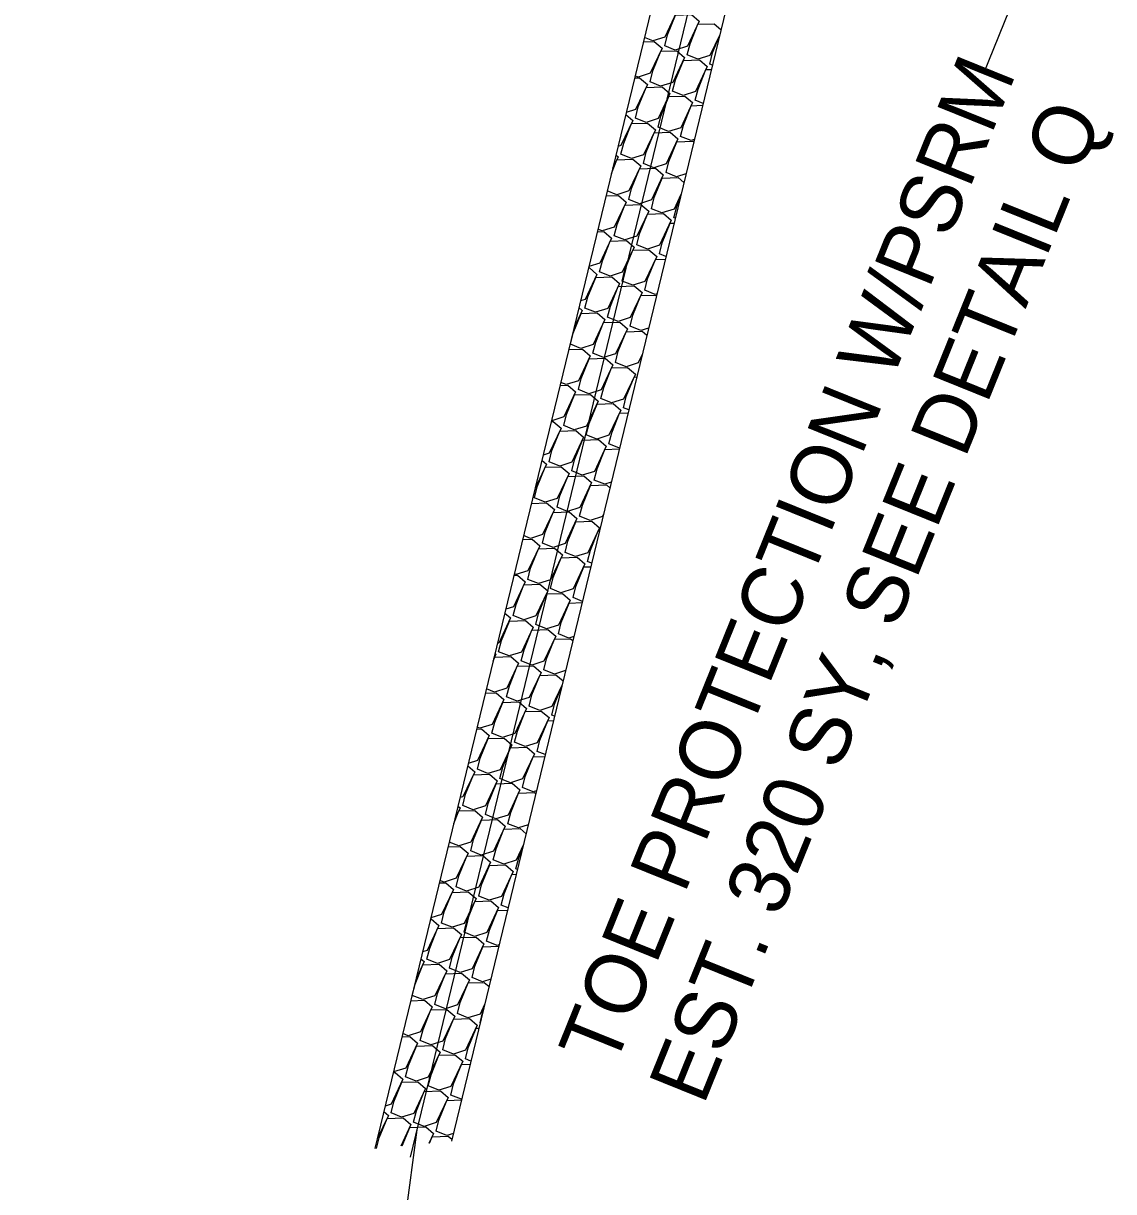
# Model space of a CAD drawing. Extents: x 2384780 to 2405432, y 547869 to 573706.
# Drawn here: x 2395368.5 to 2395458.5, y 556433.7 to 556530.2 of the extents above; entities that cross this region are included whole.
import ezdxf

# ---------------------------------------------------------------- set-up
doc = ezdxf.new("R2010")
doc.units = 0
for name, color, linetype in [('Old_Level_18', 7, 'Continuous'), ('Old_Level_19', 7, 'Continuous'), ('Old_Level_20', 7, 'Continuous'), ('Old_Level_5', 7, 'Continuous')]:
    doc.layers.add(name, color=color, linetype=linetype)

msp = doc.modelspace()

# ---------------------------------------------------------------- linework, layer by layer
at = {"layer": 'Old_Level_18'}
msp.add_line((2395437.477, 556589.14), (2395400.485, 556436.558), dxfattribs=at)
at = {"layer": 'Old_Level_19'}
msp.add_line((2395401.03, 556438.804), (2395368.546, 556196.083), dxfattribs=at)
at = {"layer": 'Old_Level_20'}
for p, q in [((2395434.562, 556589.846), (2395397.57, 556437.265)), ((2395440.393, 556588.433), (2395403.889, 556437.867))]:
    msp.add_line(p, q, dxfattribs=at)
for points in [[(2395420.339, 556531.18), (2395420.508, 556531.601), (2395421.833, 556531.648), (2395422.473, 556531.098), (2395421.499, 556529.033), (2395420.497, 556528.715), (2395419.809, 556528.993)], [(2395421.489, 556528.314), (2395421.72, 556529.235), (2395422.372, 556530.848), (2395423.697, 556530.895), (2395424.337, 556530.345), (2395423.362, 556528.28), (2395422.36, 556527.962), (2395421.489, 556528.314)], [(2395423.353, 556527.561), (2395423.584, 556528.481), (2395424.236, 556530.095), (2395425.56, 556530.142), (2395426.132, 556529.652)], [(2395426.029, 556529.228), (2395425.226, 556527.527), (2395424.224, 556527.209), (2395423.353, 556527.561)], [(2395419.72, 556528.63), (2395420.627, 556528.663), (2395421.267, 556528.113), (2395420.292, 556526.047), (2395419.291, 556525.73), (2395419.041, 556525.83)], [(2395425.216, 556526.808), (2395425.448, 556527.728), (2395425.992, 556529.075)], [(2395420.283, 556525.329), (2395420.514, 556526.249), (2395421.166, 556527.862), (2395422.49, 556527.91), (2395423.131, 556527.36), (2395422.156, 556525.294), (2395421.154, 556524.976), (2395420.283, 556525.329)], [(2395422.146, 556524.576), (2395422.378, 556525.496), (2395423.03, 556527.109), (2395424.354, 556527.157), (2395424.995, 556526.607), (2395424.02, 556524.542), (2395423.018, 556524.224), (2395422.146, 556524.576)], [(2395424.01, 556523.823), (2395424.242, 556524.743), (2395424.893, 556526.356), (2395425.337, 556526.372)], [(2395425.422, 556526.725), (2395425.216, 556526.808)], [(2395419.001, 556525.662), (2395419.42, 556525.677), (2395420.061, 556525.127), (2395419.086, 556523.062), (2395418.311, 556522.816)], [(2395419.076, 556522.343), (2395419.308, 556523.264), (2395419.96, 556524.877), (2395421.284, 556524.924), (2395421.925, 556524.374), (2395420.95, 556522.309), (2395419.948, 556521.991), (2395419.076, 556522.343)], [(2395420.94, 556521.59), (2395421.172, 556522.51), (2395421.823, 556524.124), (2395423.147, 556524.171), (2395423.788, 556523.621), (2395422.814, 556521.556), (2395421.811, 556521.238), (2395420.94, 556521.59)], [(2395422.804, 556520.837), (2395423.035, 556521.758), (2395423.687, 556523.371), (2395424.618, 556523.404)], [(2395424.656, 556523.562), (2395424.01, 556523.823)], [(2395418.269, 556522.644), (2395418.855, 556522.142), (2395417.88, 556520.076), (2395417.627, 556519.996)], [(2395417.87, 556519.358), (2395418.102, 556520.278), (2395418.754, 556521.891), (2395420.078, 556521.939), (2395420.718, 556521.389), (2395419.744, 556519.323), (2395418.742, 556519.005), (2395417.87, 556519.358)], [(2395419.734, 556518.605), (2395419.965, 556519.525), (2395420.617, 556521.138), (2395421.941, 556521.186), (2395422.582, 556520.636), (2395421.607, 556518.57), (2395420.605, 556518.253), (2395419.734, 556518.605)], [(2395421.598, 556517.852), (2395421.829, 556518.772), (2395422.481, 556520.385), (2395423.805, 556520.433), (2395423.882, 556520.367)], [(2395423.93, 556520.566), (2395423.675, 556520.485), (2395422.804, 556520.837)], [(2395417.086, 556517.764), (2395417.547, 556518.906), (2395418.871, 556518.953), (2395419.512, 556518.403), (2395418.538, 556516.338), (2395417.536, 556516.02), (2395416.741, 556516.341)], [(2395417.462, 556519.316), (2395417.649, 556519.156), (2395417.186, 556518.176)], [(2395418.527, 556515.619), (2395418.759, 556516.539), (2395419.411, 556518.153), (2395420.735, 556518.2), (2395421.376, 556517.65), (2395420.401, 556515.585), (2395419.399, 556515.267), (2395418.527, 556515.619)], [(2395423.246, 556517.746), (2395422.469, 556517.5), (2395421.598, 556517.852)], [(2395420.391, 556514.866), (2395420.623, 556515.787), (2395421.274, 556517.4), (2395422.599, 556517.447), (2395423.075, 556517.039)], [(2395416.641, 556515.931), (2395417.665, 556515.968), (2395418.306, 556515.417), (2395417.331, 556513.352), (2395416.329, 556513.035), (2395415.974, 556513.178)], [(2395422.831, 556516.032), (2395422.265, 556514.832), (2395421.263, 556514.514), (2395420.391, 556514.866)], [(2395422.255, 556514.113), (2395422.487, 556515.034), (2395422.743, 556515.667)], [(2395417.321, 556512.634), (2395417.553, 556513.554), (2395418.205, 556515.167), (2395419.529, 556515.215), (2395420.169, 556514.664), (2395419.195, 556512.599), (2395418.193, 556512.282), (2395417.321, 556512.634)], [(2395419.185, 556511.881), (2395419.416, 556512.801), (2395420.068, 556514.414), (2395421.393, 556514.462), (2395422.033, 556513.912), (2395421.059, 556511.846), (2395420.056, 556511.529), (2395419.185, 556511.881)], [(2395421.049, 556511.128), (2395421.28, 556512.048), (2395421.932, 556513.661), (2395422.259, 556513.673)], [(2395422.356, 556514.072), (2395422.255, 556514.113)], [(2395415.922, 556512.963), (2395416.459, 556512.982), (2395417.1, 556512.432), (2395416.125, 556510.367), (2395415.223, 556510.081)], [(2395416.115, 556509.648), (2395416.347, 556510.568), (2395416.999, 556512.182), (2395418.323, 556512.229), (2395418.963, 556511.679), (2395417.989, 556509.614), (2395416.987, 556509.296), (2395416.115, 556509.648)], [(2395417.979, 556508.895), (2395418.21, 556509.816), (2395418.862, 556511.429), (2395420.186, 556511.476), (2395420.827, 556510.926), (2395419.852, 556508.861), (2395418.85, 556508.543), (2395417.979, 556508.895)], [(2395421.59, 556510.909), (2395421.049, 556511.128)], [(2395415.202, 556509.995), (2395415.253, 556509.997), (2395415.894, 556509.446), (2395414.919, 556507.381), (2395414.539, 556507.261)], [(2395419.842, 556508.142), (2395420.074, 556509.062), (2395420.726, 556510.676), (2395421.54, 556510.705)], [(2395414.909, 556506.662), (2395415.141, 556507.583), (2395415.792, 556509.196), (2395417.117, 556509.243), (2395417.757, 556508.694), (2395416.783, 556506.628), (2395415.78, 556506.311), (2395414.909, 556506.662)], [(2395416.772, 556505.91), (2395417.004, 556506.83), (2395417.656, 556508.443), (2395418.98, 556508.49), (2395419.621, 556507.941), (2395418.646, 556505.875), (2395417.644, 556505.557), (2395416.772, 556505.91)], [(2395420.844, 556507.831), (2395420.714, 556507.79), (2395419.842, 556508.142)], [(2395418.636, 556505.157), (2395418.868, 556506.077), (2395419.519, 556507.69), (2395420.821, 556507.737)], [(2395413.703, 556503.677), (2395413.934, 556504.597), (2395414.586, 556506.211), (2395415.91, 556506.258), (2395416.551, 556505.708), (2395415.576, 556503.643), (2395414.574, 556503.325), (2395413.703, 556503.677)], [(2395414.405, 556506.704), (2395414.687, 556506.461), (2395413.985, 556504.973)], [(2395415.566, 556502.924), (2395415.798, 556503.844), (2395416.45, 556505.458), (2395417.774, 556505.505), (2395418.414, 556504.955), (2395417.44, 556502.89), (2395416.438, 556502.572), (2395415.566, 556502.924)], [(2395420.16, 556505.012), (2395419.508, 556504.804), (2395418.636, 556505.157)], [(2395417.43, 556502.171), (2395417.661, 556503.091), (2395418.313, 556504.705), (2395419.638, 556504.752), (2395420.018, 556504.425)], [(2395413.563, 556503.231), (2395414.704, 556503.272), (2395415.345, 556502.723), (2395414.37, 556500.657), (2395413.368, 556500.34), (2395412.907, 556500.526)], [(2395414.36, 556499.939), (2395414.592, 556500.859), (2395415.243, 556502.472), (2395416.567, 556502.52), (2395417.208, 556501.97), (2395416.234, 556499.904), (2395415.232, 556499.586), (2395414.36, 556499.939)], [(2395419.633, 556502.835), (2395419.303, 556502.137), (2395418.302, 556501.819), (2395417.43, 556502.171)], [(2395416.224, 556499.186), (2395416.455, 556500.106), (2395417.107, 556501.719), (2395418.431, 556501.767), (2395419.072, 556501.216), (2395418.097, 556499.151), (2395417.095, 556498.834), (2395416.224, 556499.186)], [(2395412.843, 556500.264), (2395413.498, 556500.287), (2395414.138, 556499.737), (2395413.164, 556497.672), (2395412.162, 556497.354), (2395412.14, 556497.363)], [(2395418.087, 556498.433), (2395418.319, 556499.353), (2395418.971, 556500.966), (2395419.182, 556500.974)], [(2395413.154, 556496.953), (2395413.385, 556497.873), (2395414.037, 556499.486), (2395415.362, 556499.534), (2395416.002, 556498.984), (2395415.027, 556496.919), (2395414.025, 556496.601), (2395413.154, 556496.953)], [(2395415.018, 556496.2), (2395415.249, 556497.12), (2395415.901, 556498.733), (2395417.225, 556498.781), (2395417.866, 556498.231), (2395416.891, 556496.166), (2395415.889, 556495.848), (2395415.018, 556496.2)], [(2395418.524, 556498.257), (2395418.087, 556498.433)], [(2395412.124, 556497.296), (2395412.291, 556497.302), (2395412.932, 556496.752), (2395411.958, 556494.686), (2395411.452, 556494.526)], [(2395416.881, 556495.447), (2395417.113, 556496.367), (2395417.765, 556497.981), (2395418.462, 556498.006)], [(2395411.948, 556493.968), (2395412.179, 556494.888), (2395412.831, 556496.501), (2395414.155, 556496.549), (2395414.796, 556495.998), (2395413.821, 556493.933), (2395412.819, 556493.615), (2395411.948, 556493.968)], [(2395413.811, 556493.215), (2395414.043, 556494.135), (2395414.695, 556495.748), (2395416.019, 556495.796), (2395416.66, 556495.245), (2395415.685, 556493.18), (2395414.683, 556492.863), (2395413.811, 556493.215)], [(2395417.758, 556495.096), (2395417.753, 556495.095), (2395416.881, 556495.447)], [(2395415.675, 556492.461), (2395415.907, 556493.382), (2395416.558, 556494.995), (2395417.743, 556495.037)], [(2395410.741, 556490.982), (2395410.973, 556491.902), (2395411.625, 556493.515), (2395412.949, 556493.563), (2395413.59, 556493.013), (2395412.615, 556490.948), (2395411.613, 556490.63), (2395410.741, 556490.982)], [(2395411.347, 556494.091), (2395411.726, 556493.766), (2395410.784, 556491.769)], [(2395412.605, 556490.229), (2395412.837, 556491.149), (2395413.488, 556492.762), (2395414.812, 556492.81), (2395415.453, 556492.26), (2395414.479, 556490.195), (2395413.476, 556489.877), (2395412.605, 556490.229)], [(2395417.074, 556492.277), (2395416.547, 556492.11), (2395415.675, 556492.461)], [(2395414.469, 556489.476), (2395414.7, 556490.396), (2395415.352, 556492.01), (2395416.676, 556492.057), (2395416.962, 556491.812)], [(2395410.484, 556490.532), (2395411.743, 556490.578), (2395412.383, 556490.027), (2395411.409, 556487.962), (2395410.407, 556487.644), (2395409.839, 556487.873)], [(2395411.399, 556487.243), (2395411.63, 556488.164), (2395412.282, 556489.777), (2395413.606, 556489.824), (2395414.247, 556489.275), (2395413.272, 556487.209), (2395412.27, 556486.891), (2395411.399, 556487.243)], [(2395416.435, 556489.638), (2395416.342, 556489.442), (2395415.34, 556489.124), (2395414.469, 556489.476)], [(2395413.263, 556486.49), (2395413.494, 556487.411), (2395414.146, 556489.024), (2395415.47, 556489.071), (2395416.11, 556488.522), (2395415.136, 556486.456), (2395414.134, 556486.139), (2395413.263, 556486.49)], [(2395415.126, 556485.738), (2395415.358, 556486.658), (2395416.01, 556488.271), (2395416.104, 556488.275)], [(2395409.764, 556487.564), (2395410.536, 556487.592), (2395411.177, 556487.042), (2395410.203, 556484.976), (2395409.201, 556484.659), (2395409.073, 556484.711)], [(2395410.192, 556484.258), (2395410.424, 556485.178), (2395411.076, 556486.792), (2395412.4, 556486.839), (2395413.041, 556486.289), (2395412.066, 556484.223), (2395411.064, 556483.906), (2395410.192, 556484.258)], [(2395412.056, 556483.505), (2395412.288, 556484.425), (2395412.939, 556486.039), (2395414.264, 556486.086), (2395414.904, 556485.536), (2395413.93, 556483.471), (2395412.928, 556483.153), (2395412.056, 556483.505)], [(2395415.457, 556485.604), (2395415.126, 556485.738)], [(2395413.92, 556482.752), (2395414.152, 556483.672), (2395414.803, 556485.285), (2395415.385, 556485.306)], [(2395409.044, 556484.596), (2395409.33, 556484.606), (2395409.971, 556484.056), (2395408.996, 556481.991), (2395408.365, 556481.791)], [(2395408.986, 556481.272), (2395409.218, 556482.193), (2395409.87, 556483.806), (2395411.194, 556483.853), (2395411.834, 556483.303), (2395410.86, 556481.238), (2395409.858, 556480.92), (2395408.986, 556481.272)], [(2395410.85, 556480.52), (2395411.081, 556481.44), (2395411.733, 556483.053), (2395413.058, 556483.101), (2395413.698, 556482.551), (2395412.723, 556480.485), (2395411.721, 556480.167), (2395410.85, 556480.52)], [(2395412.714, 556479.767), (2395412.945, 556480.687), (2395413.597, 556482.3), (2395414.666, 556482.338)], [(2395414.691, 556482.441), (2395413.92, 556482.752)], [(2395408.289, 556481.479), (2395408.765, 556481.071), (2395407.79, 556479.005), (2395407.681, 556478.971)], [(2395407.78, 556478.287), (2395408.012, 556479.207), (2395408.664, 556480.821), (2395409.988, 556480.868), (2395410.628, 556480.318), (2395409.654, 556478.253), (2395408.652, 556477.935), (2395407.78, 556478.287)], [(2395409.644, 556477.534), (2395409.875, 556478.454), (2395410.527, 556480.068), (2395411.851, 556480.115), (2395412.492, 556479.565), (2395411.517, 556477.5), (2395410.515, 556477.182), (2395409.644, 556477.534)], [(2395411.507, 556476.781), (2395411.739, 556477.701), (2395412.391, 556479.314), (2395413.715, 556479.362), (2395413.905, 556479.199)], [(2395413.988, 556479.542), (2395413.585, 556479.414), (2395412.714, 556479.767)], [(2395407.482, 556478.151), (2395407.559, 556478.085), (2395407.368, 556477.683)], [(2395407.328, 556477.514), (2395407.457, 556477.835), (2395408.782, 556477.882), (2395409.422, 556477.332), (2395408.448, 556475.267), (2395407.445, 556474.949), (2395406.772, 556475.221)], [(2395408.438, 556474.548), (2395408.669, 556475.468), (2395409.321, 556477.082), (2395410.645, 556477.129), (2395411.286, 556476.579), (2395410.311, 556474.514), (2395409.309, 556474.196), (2395408.438, 556474.548)], [(2395410.301, 556473.796), (2395410.533, 556474.716), (2395411.184, 556476.329), (2395412.509, 556476.377), (2395413.098, 556475.87)], [(2395413.305, 556476.723), (2395412.379, 556476.429), (2395411.507, 556476.781)], [(2395413.023, 556475.559), (2395412.175, 556473.761), (2395411.173, 556473.443), (2395410.301, 556473.796)], [(2395412.165, 556473.042), (2395412.396, 556473.963), (2395412.996, 556475.446)], [(2395406.685, 556474.865), (2395407.575, 556474.897), (2395408.216, 556474.347), (2395407.241, 556472.282), (2395406.239, 556471.964), (2395406.005, 556472.058)], [(2395407.231, 556471.563), (2395407.463, 556472.483), (2395408.115, 556474.096), (2395409.439, 556474.144), (2395410.079, 556473.594), (2395409.105, 556471.529), (2395408.103, 556471.211), (2395407.231, 556471.563)], [(2395409.095, 556470.81), (2395409.326, 556471.73), (2395409.978, 556473.343), (2395411.303, 556473.391), (2395411.943, 556472.841), (2395410.968, 556470.775), (2395409.967, 556470.458), (2395409.095, 556470.81)], [(2395410.959, 556470.057), (2395411.19, 556470.977), (2395411.842, 556472.591), (2395412.308, 556472.607)], [(2395412.391, 556472.951), (2395412.165, 556473.042)], [(2395405.966, 556471.897), (2395406.369, 556471.911), (2395407.01, 556471.361), (2395406.035, 556469.296), (2395405.277, 556469.056)], [(2395406.025, 556468.577), (2395406.257, 556469.498), (2395406.908, 556471.111), (2395408.232, 556471.158), (2395408.873, 556470.608), (2395407.899, 556468.543), (2395406.897, 556468.225), (2395406.025, 556468.577)], [(2395407.889, 556467.824), (2395408.12, 556468.745), (2395408.772, 556470.358), (2395410.096, 556470.405), (2395410.737, 556469.855), (2395409.762, 556467.79), (2395408.76, 556467.472), (2395407.889, 556467.824)], [(2395409.752, 556467.071), (2395409.984, 556467.992), (2395410.636, 556469.605), (2395411.589, 556469.639)], [(2395411.624, 556469.788), (2395410.959, 556470.057)], [(2395405.231, 556468.867), (2395405.803, 556468.376), (2395404.829, 556466.311), (2395404.593, 556466.236)], [(2395404.819, 556465.592), (2395405.05, 556466.512), (2395405.702, 556468.125), (2395407.027, 556468.173), (2395407.667, 556467.623), (2395406.692, 556465.557), (2395405.69, 556465.24), (2395404.819, 556465.592)], [(2395406.683, 556464.839), (2395406.914, 556465.759), (2395407.566, 556467.372), (2395408.89, 556467.42), (2395409.531, 556466.87), (2395408.556, 556464.804), (2395407.554, 556464.487), (2395406.683, 556464.839)], [(2395408.546, 556464.086), (2395408.778, 556465.006), (2395409.43, 556466.62), (2395410.754, 556466.667), (2395410.848, 556466.585)], [(2395410.902, 556466.807), (2395410.624, 556466.719), (2395409.752, 556467.071)], [(2395404.424, 556465.539), (2395404.597, 556465.39), (2395404.167, 556464.48)], [(2395404.075, 556464.098), (2395404.496, 556465.14), (2395405.82, 556465.187), (2395406.461, 556464.637), (2395405.486, 556462.572), (2395404.484, 556462.254), (2395403.704, 556462.569)], [(2395405.476, 556461.853), (2395405.708, 556462.774), (2395406.36, 556464.387), (2395407.684, 556464.434), (2395408.325, 556463.884), (2395407.35, 556461.819), (2395406.348, 556461.501), (2395405.476, 556461.853)], [(2395407.34, 556461.1), (2395407.572, 556462.02), (2395408.223, 556463.634), (2395409.547, 556463.681), (2395410.042, 556463.257)], [(2395410.219, 556463.988), (2395409.418, 556463.734), (2395408.546, 556464.086)], [(2395403.607, 556462.166), (2395404.614, 556462.202), (2395405.255, 556461.652), (2395404.28, 556459.586), (2395403.278, 556459.269), (2395402.938, 556459.406)], [(2395409.825, 556462.362), (2395409.214, 556461.066), (2395408.212, 556460.748), (2395407.34, 556461.1)], [(2395409.203, 556460.347), (2395409.435, 556461.267), (2395409.747, 556462.039)], [(2395404.27, 556458.868), (2395404.502, 556459.788), (2395405.154, 556461.401), (2395406.478, 556461.449), (2395407.118, 556460.899), (2395406.144, 556458.834), (2395405.141, 556458.515), (2395404.27, 556458.868)], [(2395406.134, 556458.115), (2395406.365, 556459.035), (2395407.017, 556460.648), (2395408.341, 556460.696), (2395408.982, 556460.146), (2395408.007, 556458.081), (2395407.005, 556457.763), (2395406.134, 556458.115)], [(2395407.997, 556457.362), (2395408.229, 556458.282), (2395408.881, 556459.895), (2395409.231, 556459.908)], [(2395409.325, 556460.298), (2395409.203, 556460.347)], [(2395402.887, 556459.198), (2395403.408, 556459.216), (2395404.048, 556458.666), (2395403.074, 556456.601), (2395402.189, 556456.32)], [(2395403.064, 556455.882), (2395403.295, 556456.802), (2395403.947, 556458.416), (2395405.271, 556458.463), (2395405.912, 556457.913), (2395404.937, 556455.848), (2395403.935, 556455.53), (2395403.064, 556455.882)], [(2395404.928, 556455.129), (2395405.159, 556456.049), (2395405.811, 556457.663), (2395407.135, 556457.71), (2395407.775, 556457.16), (2395406.801, 556455.095), (2395405.799, 556454.777), (2395404.928, 556455.129)], [(2395406.791, 556454.376), (2395407.023, 556455.297), (2395407.675, 556456.91), (2395408.511, 556456.94)], [(2395408.559, 556457.135), (2395407.997, 556457.362)], [(2395402.167, 556456.229), (2395402.201, 556456.231), (2395402.842, 556455.681), (2395401.868, 556453.615), (2395401.506, 556453.5)], [(2395401.857, 556452.897), (2395402.089, 556453.817), (2395402.741, 556455.43), (2395404.065, 556455.478), (2395404.706, 556454.927), (2395403.731, 556452.862), (2395402.729, 556452.544), (2395401.857, 556452.897)], [(2395403.721, 556452.144), (2395403.953, 556453.064), (2395404.604, 556454.677), (2395405.929, 556454.725), (2395406.569, 556454.175), (2395405.595, 556452.11), (2395404.593, 556451.792), (2395403.721, 556452.144)], [(2395405.585, 556451.391), (2395405.817, 556452.311), (2395406.468, 556453.924), (2395407.792, 556453.972)], [(2395407.817, 556454.073), (2395407.663, 556454.024), (2395406.791, 556454.376)], [(2395401.367, 556452.926), (2395401.636, 556452.695), (2395400.967, 556451.277)], [(2395400.651, 556449.911), (2395400.883, 556450.831), (2395401.535, 556452.445), (2395402.859, 556452.492), (2395403.499, 556451.942), (2395402.525, 556449.877), (2395401.523, 556449.559), (2395400.651, 556449.911)], [(2395402.515, 556449.158), (2395402.746, 556450.079), (2395403.398, 556451.692), (2395404.723, 556451.739), (2395405.363, 556451.189), (2395404.388, 556449.124), (2395403.387, 556448.806), (2395402.515, 556449.158)], [(2395404.379, 556448.405), (2395404.61, 556449.326), (2395405.262, 556450.939), (2395406.586, 556450.986), (2395406.985, 556450.644)], [(2395407.133, 556451.253), (2395406.456, 556451.039), (2395405.585, 556451.391)], [(2395400.528, 556449.466), (2395401.653, 556449.507), (2395402.293, 556448.956), (2395401.319, 556446.891), (2395400.317, 556446.574), (2395399.87, 556446.754)], [(2395406.627, 556449.166), (2395406.252, 556448.371), (2395405.25, 556448.053), (2395404.379, 556448.405)], [(2395401.309, 556446.173), (2395401.54, 556447.093), (2395402.192, 556448.706), (2395403.516, 556448.753), (2395404.157, 556448.204), (2395403.182, 556446.138), (2395402.18, 556445.821), (2395401.309, 556446.173)], [(2395406.242, 556447.652), (2395406.474, 556448.573), (2395406.498, 556448.633)], [(2395403.172, 556445.42), (2395403.404, 556446.34), (2395404.056, 556447.953), (2395405.38, 556448.001), (2395406.021, 556447.451), (2395405.046, 556445.385), (2395404.044, 556445.068), (2395403.172, 556445.42)], [(2395405.036, 556444.667), (2395405.268, 556445.587), (2395405.919, 556447.2), (2395406.153, 556447.209)], [(2395406.259, 556447.645), (2395406.242, 556447.652)], [(2395399.808, 556446.498), (2395400.447, 556446.521), (2395401.087, 556445.971), (2395400.113, 556443.906), (2395399.11, 556443.588), (2395399.103, 556443.591)], [(2395400.103, 556443.187), (2395400.334, 556444.107), (2395400.986, 556445.721), (2395402.31, 556445.768), (2395402.951, 556445.218), (2395401.976, 556443.153), (2395400.974, 556442.835), (2395400.103, 556443.187)], [(2395401.966, 556442.434), (2395402.198, 556443.355), (2395402.85, 556444.968), (2395404.174, 556445.015), (2395404.814, 556444.465), (2395403.84, 556442.4), (2395402.838, 556442.082), (2395401.966, 556442.434)], [(2395403.83, 556441.681), (2395404.061, 556442.601), (2395404.713, 556444.215), (2395405.434, 556444.24)], [(2395405.492, 556444.482), (2395405.036, 556444.667)], [(2395399.089, 556443.53), (2395399.24, 556443.535), (2395399.881, 556442.986), (2395398.906, 556440.92), (2395398.418, 556440.765)], [(2395398.896, 556440.201), (2395399.128, 556441.122), (2395399.78, 556442.735), (2395401.104, 556442.782), (2395401.745, 556442.233), (2395400.77, 556440.167), (2395399.768, 556439.85), (2395398.896, 556440.201)], [(2395400.76, 556439.449), (2395400.992, 556440.369), (2395401.643, 556441.982), (2395402.968, 556442.03), (2395403.608, 556441.48), (2395402.633, 556439.414), (2395401.632, 556439.096), (2395400.76, 556439.449)], [(2395404.731, 556441.338), (2395404.701, 556441.329), (2395403.83, 556441.681)], [(2395402.624, 556438.696), (2395402.855, 556439.616), (2395403.507, 556441.229), (2395404.715, 556441.272)], [(2395397.706, 556437.278), (2395397.922, 556438.136), (2395398.573, 556439.75), (2395399.897, 556439.797), (2395400.538, 556439.247), (2395399.698, 556437.468)], [(2395398.309, 556440.314), (2395398.675, 556440), (2395397.766, 556438.074)], [(2395399.824, 556437.48), (2395400.437, 556438.997), (2395401.761, 556439.044), (2395402.402, 556438.494), (2395402.022, 556437.689)], [(2395404.047, 556438.519), (2395403.495, 556438.343), (2395402.624, 556438.696)], [(2395402.079, 556437.695), (2395402.301, 556438.244), (2395403.625, 556438.291), (2395403.929, 556438.03)]]:
    msp.add_lwpolyline(points, dxfattribs=at)
at = {"layer": 'Old_Level_5'}
msp.add_line((2395447.84, 556526.068), (2395451.586, 556535.339), dxfattribs=at)

# ---------------------------------------------------------------- texts
for s, p in [('TOE PROTECTION W/PSRM', (2395417.275, 556443.744)), ('EST. 320 SY, SEE DETAIL Q', (2395424.693, 556440.747))]:
    msp.add_text(s, height=5, rotation=68.00009, dxfattribs=at).set_placement(p)

doc.saveas('drawing.dxf')
